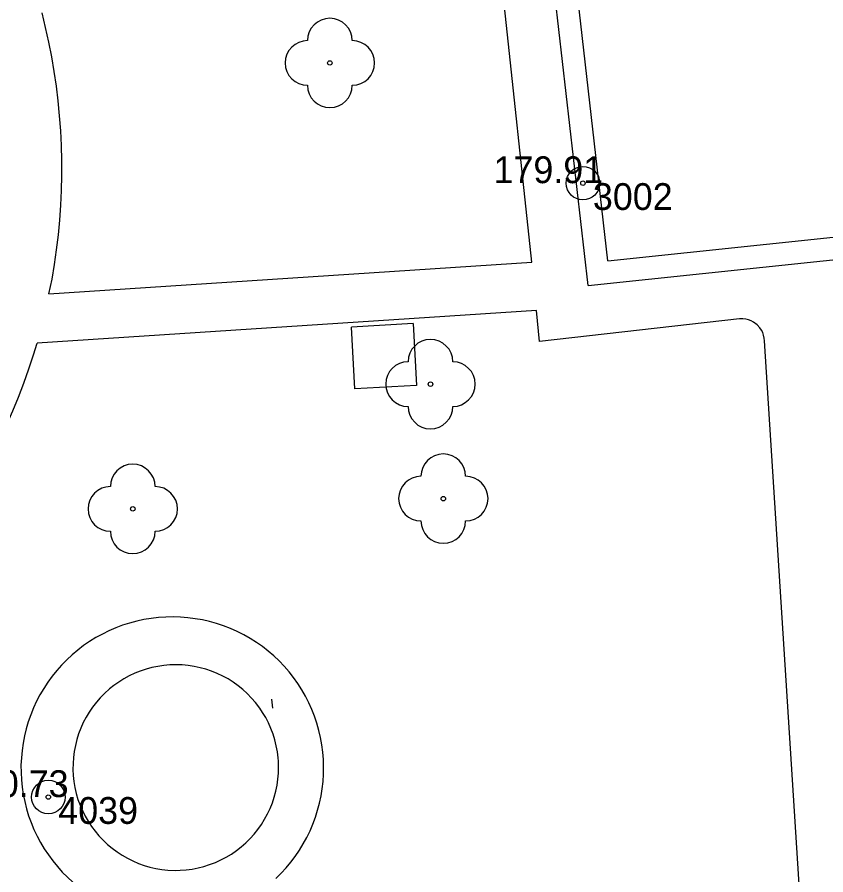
# Model space of a CAD drawing. Extents: x -539515 to -538098, y -1182060 to -1180157.
# Drawn here: x -539344.99 to -539326.9, y -1181187.01 to -1181167.81 of the extents above; entities that cross this region are included whole.
import ezdxf

# ---------------------------------------------------------------- set-up
doc = ezdxf.new("R2010")
doc.units = 0
for name, color, linetype in [('Vrstva 10', 7, 'Continuous'), ('Vrstva 11', 7, 'Continuous'), ('Vrstva 21', 7, 'Continuous'), ('Vrstva 22', 7, 'Continuous'), ('Vrstva 23', 7, 'Continuous'), ('Vrstva 5', 7, 'Continuous')]:
    doc.layers.add(name, color=color, linetype=linetype)

msp = doc.modelspace()

# ---------------------------------------------------------------- linework, layer by layer
at = {"layer": 'Vrstva 10'}
msp.add_line((-539339.269, -1181183.281), (-539339.289, -1181183.082), dxfattribs=at)
at = {"layer": 'Vrstva 11'}
for p, q in [((-539333.47, -1181173.3), (-539335.63, -1181153.14)), ((-539344.28, -1181174.01), (-539333.47, -1181173.3)), ((-539333.37, -1181174.38), (-539344.54, -1181175.11)), ((-539333.3, -1181175.07), (-539333.37, -1181174.38)), ((-539328.83, -1181174.57), (-539333.3, -1181175.07)), ((-539327.43, -1181188.19), (-539328.27, -1181175.06))]:
    msp.add_line(p, q, dxfattribs=at)
for points in [[(-539344.28, -1181174.01), (-539344.207, -1181173.681), (-539344.152, -1181173.352), (-539344.104, -1181173.022), (-539344.065, -1181172.69), (-539344.033, -1181172.357), (-539344.01, -1181172.024), (-539343.994, -1181171.691), (-539343.987, -1181171.357), (-539343.987, -1181171.023), (-539343.996, -1181170.689), (-539344.012, -1181170.356), (-539344.037, -1181170.023), (-539344.069, -1181169.69), (-539344.109, -1181169.359), (-539344.158, -1181169.028), (-539344.214, -1181168.699), (-539344.278, -1181168.371), (-539344.35, -1181168.045), (-539344.43, -1181167.721)], [(-539328.27, -1181175.06), (-539328.275, -1181174.997), (-539328.288, -1181174.935), (-539328.308, -1181174.875), (-539328.336, -1181174.818), (-539328.371, -1181174.766), (-539328.43, -1181174.7), (-539328.511, -1181174.639), (-539328.567, -1181174.61), (-539328.626, -1181174.588), (-539328.688, -1181174.573), (-539328.751, -1181174.567), (-539328.83, -1181174.57)], [(-539344.837, -1181176.004), (-539344.725, -1181175.689), (-539344.622, -1181175.372), (-539344.54, -1181175.11)], [(-539345.503, -1181177.534), (-539345.355, -1181177.235), (-539345.215, -1181176.932), (-539345.081, -1181176.626), (-539344.955, -1181176.316), (-539344.837, -1181176.004)], [(-539341.333, -1181181.243), (-539341.497, -1181181.238), (-539341.662, -1181181.241), (-539341.826, -1181181.252), (-539341.989, -1181181.271), (-539342.152, -1181181.298), (-539342.312, -1181181.333), (-539342.471, -1181181.376), (-539342.628, -1181181.426), (-539342.782, -1181181.484), (-539342.933, -1181181.549), (-539343.081, -1181181.621), (-539343.225, -1181181.701), (-539343.365, -1181181.787), (-539343.501, -1181181.881), (-539343.631, -1181181.98), (-539343.757, -1181182.086), (-539343.878, -1181182.198), (-539343.993, -1181182.316), (-539344.102, -1181182.439), (-539344.205, -1181182.567), (-539344.302, -1181182.7), (-539344.392, -1181182.838), (-539344.476, -1181182.98), (-539344.552, -1181183.126), (-539344.621, -1181183.275), (-539344.683, -1181183.428), (-539344.737, -1181183.583), (-539344.784, -1181183.741), (-539344.823, -1181183.901), (-539344.855, -1181184.062), (-539344.878, -1181184.225), (-539344.893, -1181184.389), (-539344.901, -1181184.553), (-539344.9, -1181184.718)], [(-539339.197, -1181187.091), (-539339.08, -1181186.976), (-539338.969, -1181186.855), (-539338.863, -1181186.728), (-539338.764, -1181186.597), (-539338.672, -1181186.461), (-539338.586, -1181186.32), (-539338.507, -1181186.176), (-539338.435, -1181186.028), (-539338.37, -1181185.877), (-539338.313, -1181185.722), (-539338.264, -1181185.565), (-539338.222, -1181185.406), (-539338.187, -1181185.245), (-539338.161, -1181185.083), (-539338.143, -1181184.919), (-539338.132, -1181184.755), (-539338.13, -1181184.591), (-539338.136, -1181184.426), (-539338.149, -1181184.262), (-539338.171, -1181184.099), (-539338.2, -1181183.937), (-539338.238, -1181183.777), (-539338.283, -1181183.618), (-539338.335, -1181183.462), (-539338.395, -1181183.309), (-539338.463, -1181183.159), (-539338.538, -1181183.013), (-539338.619, -1181182.87), (-539338.708, -1181182.731), (-539338.803, -1181182.597), (-539338.905, -1181182.468), (-539339.013, -1181182.343), (-539339.127, -1181182.224), (-539339.246, -1181182.111), (-539339.371, -1181182.004), (-539339.501, -1181181.903), (-539339.635, -1181181.808), (-539339.774, -1181181.72), (-539339.917, -1181181.639), (-539340.064, -1181181.565), (-539340.215, -1181181.498), (-539340.368, -1181181.438), (-539340.524, -1181181.386), (-539340.683, -1181181.342), (-539340.843, -1181181.305), (-539341.005, -1181181.277), (-539341.168, -1181181.256), (-539341.333, -1181181.243)], [(-539344.9, -1181184.718), (-539344.892, -1181184.882), (-539344.875, -1181185.046), (-539344.85, -1181185.209), (-539344.818, -1181185.37), (-539344.778, -1181185.53), (-539344.73, -1181185.687)], [(-539344.73, -1181185.687), (-539344.675, -1181185.842), (-539344.612, -1181185.994), (-539344.541, -1181186.143), (-539344.464, -1181186.288), (-539344.38, -1181186.429), (-539344.289, -1181186.566), (-539344.191, -1181186.699), (-539344.087, -1181186.826), (-539343.977, -1181186.949), (-539343.861, -1181187.066), (-539343.739, -1181187.177), (-539343.613, -1181187.282), (-539343.481, -1181187.38), (-539343.345, -1181187.473), (-539343.204, -1181187.558), (-539343.06, -1181187.637), (-539342.911, -1181187.708), (-539342.76, -1181187.772), (-539342.605, -1181187.829), (-539342.448, -1181187.878), (-539342.289, -1181187.92), (-539342.128, -1181187.953), (-539342.03, -1181187.97)]]:
    msp.add_lwpolyline(points, dxfattribs=at)
at = {"layer": 'Vrstva 21'}
for centre, radius in [((-539332.33, -1181171.53), 0.375), ((-539332.33, -1181171.53), 0.05), ((-539344.29, -1181185.27), 0.375), ((-539344.29, -1181185.27), 0.05)]:
    msp.add_circle(centre, radius, dxfattribs=at)
at = {"layer": 'Vrstva 22'}
for centre in [(-539337.991, -1181168.839), (-539335.74, -1181176.028), (-539335.453, -1181178.59), (-539342.4, -1181178.82)]:
    msp.add_circle(centre, 0.05, dxfattribs=at)
for centre, start, end in [((-539337.991, -1181168.339), 0, 180), ((-539338.491, -1181168.839), 90, 270), ((-539337.491, -1181168.839), 270, 90), ((-539337.991, -1181169.339), 180, 0), ((-539335.74, -1181175.528), 0, 180), ((-539336.24, -1181176.028), 90, 270), ((-539335.24, -1181176.028), 270, 90), ((-539335.74, -1181176.528), 180, 0), ((-539335.453, -1181178.09), 0, 180), ((-539342.4, -1181178.32), 0, 180), ((-539335.953, -1181178.59), 90, 270), ((-539334.953, -1181178.59), 270, 90), ((-539342.9, -1181178.82), 90, 270), ((-539341.9, -1181178.82), 270, 90), ((-539335.453, -1181179.09), 180, 0), ((-539342.4, -1181179.32), 180, 0)]:
    msp.add_arc(centre, 0.5, start, end, dxfattribs=at)
at = {"layer": 'Vrstva 5'}
for p, q in [((-539332.21, -1181173.82), (-539334.12, -1181157.16)), ((-539331.77, -1181173.271), (-539333.566, -1181157.605)), ((-539331.77, -1181173.271), (-539300.782, -1181170.015)), ((-539336.13, -1181174.67), (-539337.51, -1181174.75)), ((-539337.43, -1181176.13), (-539337.51, -1181174.75)), ((-539336.13, -1181174.67), (-539336.05, -1181176.06)), ((-539336.05, -1181176.06), (-539337.43, -1181176.13)), ((-539342.231, -1181182.45), (-539342.357, -1181182.5)), ((-539342.102, -1181182.407), (-539342.231, -1181182.45)), ((-539341.971, -1181182.371), (-539342.102, -1181182.407)), ((-539341.838, -1181182.344), (-539341.971, -1181182.371)), ((-539341.704, -1181182.324), (-539341.838, -1181182.344)), ((-539341.569, -1181182.313), (-539341.704, -1181182.324)), ((-539341.433, -1181182.309), (-539341.569, -1181182.313)), ((-539341.298, -1181182.313), (-539341.433, -1181182.309)), ((-539341.163, -1181182.325), (-539341.298, -1181182.313)), ((-539341.028, -1181182.345), (-539341.163, -1181182.325)), ((-539340.896, -1181182.374), (-539341.028, -1181182.345)), ((-539340.765, -1181182.409), (-539340.896, -1181182.374)), ((-539340.636, -1181182.453), (-539340.765, -1181182.409)), ((-539340.511, -1181182.504), (-539340.636, -1181182.453)), ((-539342.598, -1181182.623), (-539342.713, -1181182.695)), ((-539342.479, -1181182.558), (-539342.598, -1181182.623)), ((-539342.357, -1181182.5), (-539342.479, -1181182.558)), ((-539340.388, -1181182.562), (-539340.511, -1181182.504)), ((-539340.269, -1181182.627), (-539340.388, -1181182.562)), ((-539340.155, -1181182.7), (-539340.269, -1181182.627)), ((-539342.92, -1181182.85), (-539343.03, -1181182.949)), ((-539342.824, -1181182.773), (-539342.92, -1181182.85)), ((-539342.713, -1181182.695), (-539342.824, -1181182.773)), ((-539340.044, -1181182.779), (-539340.155, -1181182.7)), ((-539339.939, -1181182.864), (-539340.044, -1181182.779)), ((-539343.126, -1181183.046), (-539343.215, -1181183.148)), ((-539343.03, -1181182.949), (-539343.126, -1181183.046)), ((-539339.839, -1181182.955), (-539339.939, -1181182.864)), ((-539339.744, -1181183.053), (-539339.839, -1181182.955)), ((-539343.215, -1181183.148), (-539343.298, -1181183.256)), ((-539339.655, -1181183.155), (-539339.744, -1181183.053)), ((-539339.56, -1181183.28), (-539339.655, -1181183.155)), ((-539343.374, -1181183.368), (-539343.444, -1181183.484)), ((-539343.298, -1181183.256), (-539343.374, -1181183.368)), ((-539339.496, -1181183.375), (-539339.56, -1181183.28)), ((-539339.427, -1181183.491), (-539339.496, -1181183.375)), ((-539343.507, -1181183.604), (-539343.563, -1181183.728)), ((-539343.444, -1181183.484), (-539343.507, -1181183.604)), ((-539339.365, -1181183.612), (-539339.427, -1181183.491)), ((-539339.309, -1181183.736), (-539339.365, -1181183.612)), ((-539343.563, -1181183.728), (-539343.611, -1181183.855)), ((-539339.262, -1181183.863), (-539339.309, -1181183.736)), ((-539343.652, -1181183.984), (-539343.685, -1181184.116)), ((-539343.611, -1181183.855), (-539343.652, -1181183.984)), ((-539339.221, -1181183.992), (-539339.262, -1181183.863)), ((-539339.189, -1181184.124), (-539339.221, -1181183.992)), ((-539343.685, -1181184.116), (-539343.71, -1181184.249)), ((-539339.164, -1181184.257), (-539339.189, -1181184.124)), ((-539343.727, -1181184.383), (-539343.736, -1181184.519)), ((-539343.71, -1181184.249), (-539343.727, -1181184.383)), ((-539339.147, -1181184.392), (-539339.164, -1181184.257)), ((-539343.736, -1181184.519), (-539343.738, -1181184.654)), ((-539343.738, -1181184.654), (-539343.731, -1181184.79)), ((-539343.731, -1181184.79), (-539343.717, -1181184.925)), ((-539343.717, -1181184.925), (-539343.694, -1181185.058)), ((-539343.694, -1181185.058), (-539343.664, -1181185.191)), ((-539343.664, -1181185.191), (-539343.626, -1181185.321)), ((-539343.626, -1181185.321), (-539343.58, -1181185.449)), ((-539339.277, -1181185.399), (-539339.234, -1181185.271)), ((-539343.58, -1181185.449), (-539343.527, -1181185.573)), ((-539339.385, -1181185.648), (-539339.327, -1181185.525)), ((-539339.327, -1181185.525), (-539339.277, -1181185.399)), ((-539343.527, -1181185.573), (-539343.466, -1181185.695)), ((-539343.466, -1181185.695), (-539343.399, -1181185.812)), ((-539339.45, -1181185.767), (-539339.385, -1181185.648)), ((-539343.399, -1181185.812), (-539343.324, -1181185.926)), ((-539343.324, -1181185.926), (-539343.244, -1181186.035)), ((-539339.6, -1181185.993), (-539339.521, -1181185.882)), ((-539339.521, -1181185.882), (-539339.45, -1181185.767)), ((-539343.244, -1181186.035), (-539343.156, -1181186.139)), ((-539339.775, -1181186.2), (-539339.684, -1181186.099)), ((-539339.684, -1181186.099), (-539339.6, -1181185.993)), ((-539343.156, -1181186.139), (-539343.063, -1181186.237)), ((-539343.063, -1181186.237), (-539342.964, -1181186.33)), ((-539339.974, -1181186.384), (-539339.872, -1181186.295)), ((-539339.872, -1181186.295), (-539339.775, -1181186.2)), ((-539342.964, -1181186.33), (-539342.86, -1181186.417)), ((-539342.86, -1181186.417), (-539342.751, -1181186.498)), ((-539342.751, -1181186.498), (-539342.638, -1181186.572)), ((-539340.193, -1181186.544), (-539340.081, -1181186.468)), ((-539340.081, -1181186.468), (-539339.974, -1181186.384)), ((-539342.638, -1181186.572), (-539342.52, -1181186.64)), ((-539342.52, -1181186.64), (-539342.398, -1181186.7)), ((-539342.398, -1181186.7), (-539342.274, -1181186.753)), ((-539340.553, -1181186.733), (-539340.429, -1181186.677)), ((-539340.429, -1181186.677), (-539340.309, -1181186.614)), ((-539340.309, -1181186.614), (-539340.193, -1181186.544)), ((-539342.274, -1181186.753), (-539342.146, -1181186.798)), ((-539342.146, -1181186.798), (-539342.016, -1181186.836)), ((-539342.016, -1181186.836), (-539341.883, -1181186.866)), ((-539341.883, -1181186.866), (-539341.75, -1181186.889)), ((-539341.75, -1181186.889), (-539341.615, -1181186.903)), ((-539341.208, -1181186.899), (-539341.074, -1181186.881)), ((-539341.074, -1181186.881), (-539340.94, -1181186.856)), ((-539340.94, -1181186.856), (-539340.809, -1181186.822)), ((-539340.809, -1181186.822), (-539340.68, -1181186.782)), ((-539340.68, -1181186.782), (-539340.553, -1181186.733)), ((-539341.615, -1181186.903), (-539341.45, -1181186.91)), ((-539341.45, -1181186.91), (-539341.343, -1181186.908)), ((-539341.343, -1181186.908), (-539341.208, -1181186.899))]:
    msp.add_line(p, q, dxfattribs=at)
for points in [[(-539332.21, -1181173.82), (-539303.652, -1181170.82)], [(-539339.141, -1181184.466), (-539339.147, -1181184.392)], [(-539339.137, -1181184.602), (-539339.141, -1181184.466)], [(-539339.152, -1181184.872), (-539339.141, -1181184.737)], [(-539339.141, -1181184.737), (-539339.137, -1181184.602)], [(-539339.172, -1181185.007), (-539339.152, -1181184.872)], [(-539339.234, -1181185.271), (-539339.199, -1181185.14)], [(-539339.199, -1181185.14), (-539339.172, -1181185.007)]]:
    msp.add_lwpolyline(points, dxfattribs=at)

# ---------------------------------------------------------------- texts
at = {"layer": 'Vrstva 22'}
for s, p in [('179.91 ', (-539334.33, -1181171.53)), ('180.73 ', (-539346.29, -1181185.27))]:
    msp.add_text(s, height=0.6, dxfattribs=at).set_placement(p)
at = {"layer": 'Vrstva 23'}
for s, p in [(' 3002', (-539332.33, -1181172.13)), (' 4039', (-539344.29, -1181185.87))]:
    msp.add_text(s, height=0.6, dxfattribs=at).set_placement(p)

doc.saveas('drawing.dxf')
